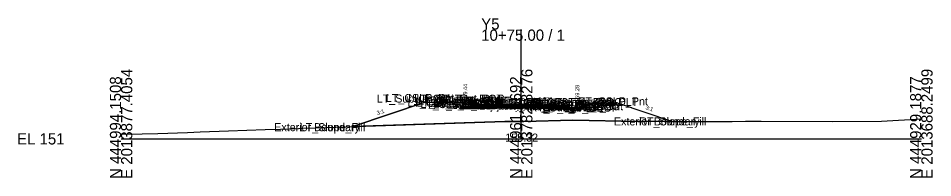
# Model space of a CAD drawing. Extents: x -26 to 203, y -10 to 4517.
# Drawn here: x -25.7 to 202.8, y 1490.3 to 1530.1 of the extents above; entities that cross this region are included whole.
import ezdxf

# ---------------------------------------------------------------- set-up
doc = ezdxf.new("R2010")
doc.units = 0
for name, color, linetype in [('Default', 7, 'Continuous'), ('Exist Cross Section Cell', 7, 'Continuous'), ('Exist XS Center Line Elevation Label', 7, 'Continuous'), ('Exist XS Ground Line', 7, 'Continuous'), ('Prop CMT Conc Surface', 7, 'Continuous'), ('Prop CMT Concrete Structures', 7, 'Continuous'), ('Prop CMT Pvmt Course 1', 7, 'Continuous'), ('Prop CMT Pvmt Course 1 CG', 7, 'Continuous'), ('Prop CMT Pvmt Course 2', 7, 'Continuous'), ('Prop CMT Pvmt Course 3', 7, 'Continuous'), ('Prop CMT Pvmt Surface', 7, 'Continuous'), ('Prop CMT Slope Grass', 7, 'Continuous'), ('Prop CMT Subgrade Earthwork', 7, 'Continuous'), ('Prop XS Earthwork Shape', 7, 'Continuous'), ('Prop XS Hydro Elevations', 7, 'Continuous'), ('Prop XS SE Text', 7, 'Continuous'), ('Prop XS Side Slope Text', 7, 'Continuous'), ('Scratch_Level_0', 7, 'Continuous')]:
    doc.layers.add(name, color=color, linetype=linetype)

msp = doc.modelspace()

# ---------------------------------------------------------------- linework, layer by layer
at = {"layer": 'Exist Cross Section Cell'}
for p, q in [((100, 1500), (100, 1527.29)), ((0, 1500), (100, 1500)), ((100, 1500), (200, 1500))]:
    msp.add_line(p, q, dxfattribs=at)
at = {"layer": 'Exist XS Ground Line'}
msp.add_lwpolyline([(0, 1501.19), (5.27, 1501.23), (9.17, 1501.3), (16.63, 1501.57), (19.74, 1501.72), (26.82, 1502), (36, 1502.31), (39.83, 1502.45), (44.34, 1502.62), (45.42, 1502.65), (48.7, 1502.78), (95.92, 1504.35), (98.71, 1504.3), (99.33, 1504.32), (100, 1504.32), (100.69, 1504.32), (112.91, 1504.69), (129.12, 1504.36), (130.02, 1504.36), (131.06, 1504.38), (135.99, 1504.36), (137.61, 1504.37), (152.72, 1504.35), (156.09, 1504.4), (159.93, 1504.45), (177.68, 1504.33), (190.01, 1504.4), (200, 1504.98)], dxfattribs=at)
at = {"layer": 'Prop CMT Conc Surface'}
for points in [[(86, 1508.51), (86, 1508.94), (85.5, 1508.94)], [(88, 1508.53), (86, 1508.44)], [(112, 1508.39), (114, 1508.27)], [(114, 1508.27), (114, 1508.77), (114.5, 1508.77)]]:
    msp.add_lwpolyline(points, dxfattribs=at)
at = {"layer": 'Prop CMT Concrete Structures'}
for points in [[(88, 1508.53), (86, 1508.44), (86, 1508.94), (85.5, 1508.94)], [(85.5, 1508.94), (85.5, 1507.93), (88, 1507.95)], [(88, 1507.95), (88, 1508.53)], [(112, 1508.39), (114, 1508.27), (114, 1508.77), (114.5, 1508.77)], [(114.5, 1508.77), (114.5, 1507.76), (112, 1507.81)], [(112, 1507.81), (112, 1508.39)]]:
    msp.add_lwpolyline(points, dxfattribs=at)
at = {"layer": 'Prop CMT Pvmt Course 1'}
for points in [[(100, 1508.63), (88, 1508.53)], [(88, 1508.53), (88, 1508.28)], [(88, 1508.28), (100, 1508.38)], [(100, 1508.38), (100, 1508.63)], [(100, 1508.63), (112, 1508.39)], [(100, 1508.38), (100, 1508.63)], [(112, 1508.14), (100, 1508.38)], [(112, 1508.39), (112, 1508.14)]]:
    msp.add_lwpolyline(points, dxfattribs=at)
msp.add_lwpolyline([(100, 1508.38), (100, 1508.51), (100, 1508.51), (100, 1508.38)], close=True, dxfattribs=at)
msp.add_lwpolyline([(100, 1508.38), (100, 1508.51), (100, 1508.51), (100, 1508.38)], close=True, dxfattribs=at)
at = {"layer": 'Prop CMT Pvmt Course 1 CG'}
for points in [[(88, 1507.95), (85, 1507.92), (84.66, 1507.59)], [(84.66, 1507.59), (88, 1507.62)], [(88, 1507.62), (88, 1507.95)], [(112, 1507.81), (115, 1507.75), (115.34, 1507.41)], [(112, 1507.48), (112, 1507.81)], [(115.34, 1507.41), (112, 1507.48)]]:
    msp.add_lwpolyline(points, dxfattribs=at)
at = {"layer": 'Prop CMT Pvmt Course 2'}
for points in [[(100, 1508.38), (88, 1508.28)], [(100, 1508.05), (100, 1508.38)], [(100, 1508.05), (100, 1508.38)], [(100, 1508.38), (112, 1508.14)], [(88, 1508.28), (88, 1507.95)], [(88, 1507.95), (100, 1508.05)], [(112, 1507.81), (100, 1508.05)], [(112, 1508.14), (112, 1507.81)]]:
    msp.add_lwpolyline(points, dxfattribs=at)
at = {"layer": 'Prop CMT Pvmt Course 3'}
for points in [[(100, 1508.05), (88, 1507.95)], [(88, 1507.95), (88, 1507.62)], [(88, 1507.62), (100, 1507.72)], [(100, 1507.72), (100, 1508.05)], [(100, 1508.05), (112, 1507.81)], [(100, 1507.72), (100, 1508.05)], [(112, 1507.48), (100, 1507.72)], [(112, 1507.81), (112, 1507.48)]]:
    msp.add_lwpolyline(points, dxfattribs=at)
at = {"layer": 'Prop CMT Pvmt Surface'}
for points in [[(100, 1508.63), (88, 1508.53)], [(100, 1508.63), (112, 1508.39)]]:
    msp.add_lwpolyline(points, dxfattribs=at)
at = {"layer": 'Prop CMT Slope Grass'}
for points in [[(85.5, 1508.94), (76, 1509.13), (57.89, 1503.09)], [(114.5, 1508.77), (124, 1508.96), (137.8, 1504.37)]]:
    msp.add_lwpolyline(points, dxfattribs=at)
at = {"layer": 'Prop CMT Subgrade Earthwork'}
for points in [[(88, 1507.62), (84.66, 1507.59), (83.27, 1508.98)], [(112, 1507.48), (115.34, 1507.41), (116.75, 1508.82)], [(100, 1507.72), (88, 1507.62)], [(100, 1507.72), (112, 1507.48)]]:
    msp.add_lwpolyline(points, dxfattribs=at)
at = {"layer": 'Prop XS Earthwork Shape'}
msp.add_lwpolyline([(112, 1507.48), (115.34, 1507.41), (116.75, 1508.82), (124, 1508.96), (137.8, 1504.37), (137.61, 1504.37), (135.99, 1504.36), (131.06, 1504.38), (130.02, 1504.36), (129.12, 1504.36), (112.91, 1504.69), (100.69, 1504.32), (100, 1504.32), (99.33, 1504.32), (98.71, 1504.3), (95.92, 1504.35), (57.89, 1503.09), (76, 1509.13), (83.27, 1508.98), (84.66, 1507.59), (88, 1507.62), (100, 1507.72)], close=True, dxfattribs=at)

# ---------------------------------------------------------------- texts
at = {"layer": 'Default'}
msp.add_text('-', height=0.0001, dxfattribs=at).set_placement((0, 1500))
at = {"layer": 'Exist Cross Section Cell'}
for s, p in [('Y5', (90, 1527.29)), ('10+75.00 / 1', (90, 1524.49)), ('EL 151', (-26, 1498.6))]:
    msp.add_text(s, height=2.8, dxfattribs=at).set_placement(p)
for s, p in [('N 444994.1508', (0, 1490)), ('E 2013877.4054', (2.8, 1490)), ('N 444961.6692', (100, 1490)), ('E 2013782.8276', (102.8, 1490)), ('N 444929.1877', (200, 1490)), ('E 2013688.2499', (202.8, 1490))]:
    msp.add_text(s, height=2.8, rotation=90, dxfattribs=at).set_placement(p)
at = {"layer": 'Exist XS Center Line Elevation Label'}
msp.add_text('155.32', height=2, dxfattribs=at).set_placement((96.03, 1499.32))
at = {"layer": 'Prop XS Hydro Elevations'}
for s, p in [('159.44', (86.5, 1509.51)), ('159.28', (114.5, 1509.25))]:
    msp.add_text(s, height=1, rotation=90, dxfattribs=at).set_placement(p)
at = {"layer": 'Prop XS SE Text'}
for s, rotation, p in [('0.009', 0.487, (92.64, 1509.49)), ('0.020', 358.8542, (104.29, 1509.49))]:
    msp.add_text(s, height=1, rotation=rotation, dxfattribs=at).set_placement(p)
at = {"layer": 'Prop XS Side Slope Text'}
for rotation, p in [(18.434, (64.08, 1505.94)), (341.5667, (131, 1507.42))]:
    msp.add_text('3:1', height=1, rotation=rotation, dxfattribs=at).set_placement(p)
at = {"layer": 'Scratch_Level_0'}
for s, p in [('LT_Sub_Trench_Out_DLT', (63.91, 1509.06)), ('LT_CSLP_Pnt', (66.18, 1509.21)), ('LT_CG_Top_Face', (73.27, 1509.02)), ('LT_CG_Top_BOC', (73.79, 1509.02)), ('LT_CG1_Shelf_Out', (71.56, 1508.05)), ('LT_CG_Bot_BOC', (73.82, 1508.03)), ('LT_CG_Top_Gut', (74.24, 1508.52)), ('LT_Sub_OEOP', (74.8, 1507.72)), ('LT_CG_Bot_IE', (77.92, 1507.96)), ('LT_Sub_OEOT', (78.09, 1507.62)), ('LT_PV2_OEOT', (78.18, 1508.29)), ('LT_PV3_OEOT', (78.18, 1507.96)), ('LT_PV1_OEOT', (78.75, 1508.54)), ('RT_Sub_OEEOP', (89.17, 1507.26)), ('LT_Sub_OEEOP', (89.22, 1507.26)), ('RT_PV2_OEEOP', (89.27, 1507.93)), ('RT_PV3_OEEOP', (89.27, 1507.6)), ('LT_PV2_OEEOP', (89.32, 1507.93)), ('LT_PV3_OEEOP', (89.32, 1507.6)), ('RT_PV1_OEEOP', (89.84, 1508.05)), ('LT_PV1_OEEOP', (89.88, 1508.05)), ('RT_PV2_IEEOP', (89.91, 1507.93)), ('LT_PV2_IEEOP', (89.96, 1507.93)), ('RT_PV1_IEEOP', (90.48, 1508.05)), ('LT_PV1_IEEOP', (90.53, 1508.05)), ('PV2_PGL', (93.91, 1507.93)), ('PV1_PGL', (94.48, 1508.18)), ('RT_Sub_Trench_Out_DLT', (97.29, 1508.22)), ('RT_CG_Top_Face', (101.22, 1508.18)), ('RT_CG1_Shelf_Out', (101.51, 1507.15)), ('RT_CG_Bot_IE', (101.87, 1507.24)), ('RT_Sub_OEOT', (102.04, 1506.9)), ('RT_PV2_OEOT', (102.13, 1507.57)), ('RT_PV3_OEOT', (102.13, 1507.24)), ('RT_CG_Top_Gut', (102.2, 1507.68)), ('RT_PV1_OEOT', (102.7, 1507.82)), ('RT_CG_Top_BOC', (102.75, 1508.18)), ('RT_CG_Bot_BOC', (102.78, 1507.16)), ('RT_Sub_OEOP', (105.41, 1506.8)), ('RT_CSLP_Pnt', (114.13, 1508.37)), ('Exterior Boundary', (38.28, 1501.92)), ('LT_Slope_Fill', (44.66, 1501.92)), ('Exterior Boundary', (123.17, 1503.36)), ('RT_Slope_Fill', (129.5, 1503.36))]:
    msp.add_text(s, height=2, dxfattribs=at).set_placement(p)

doc.saveas('drawing.dxf')
